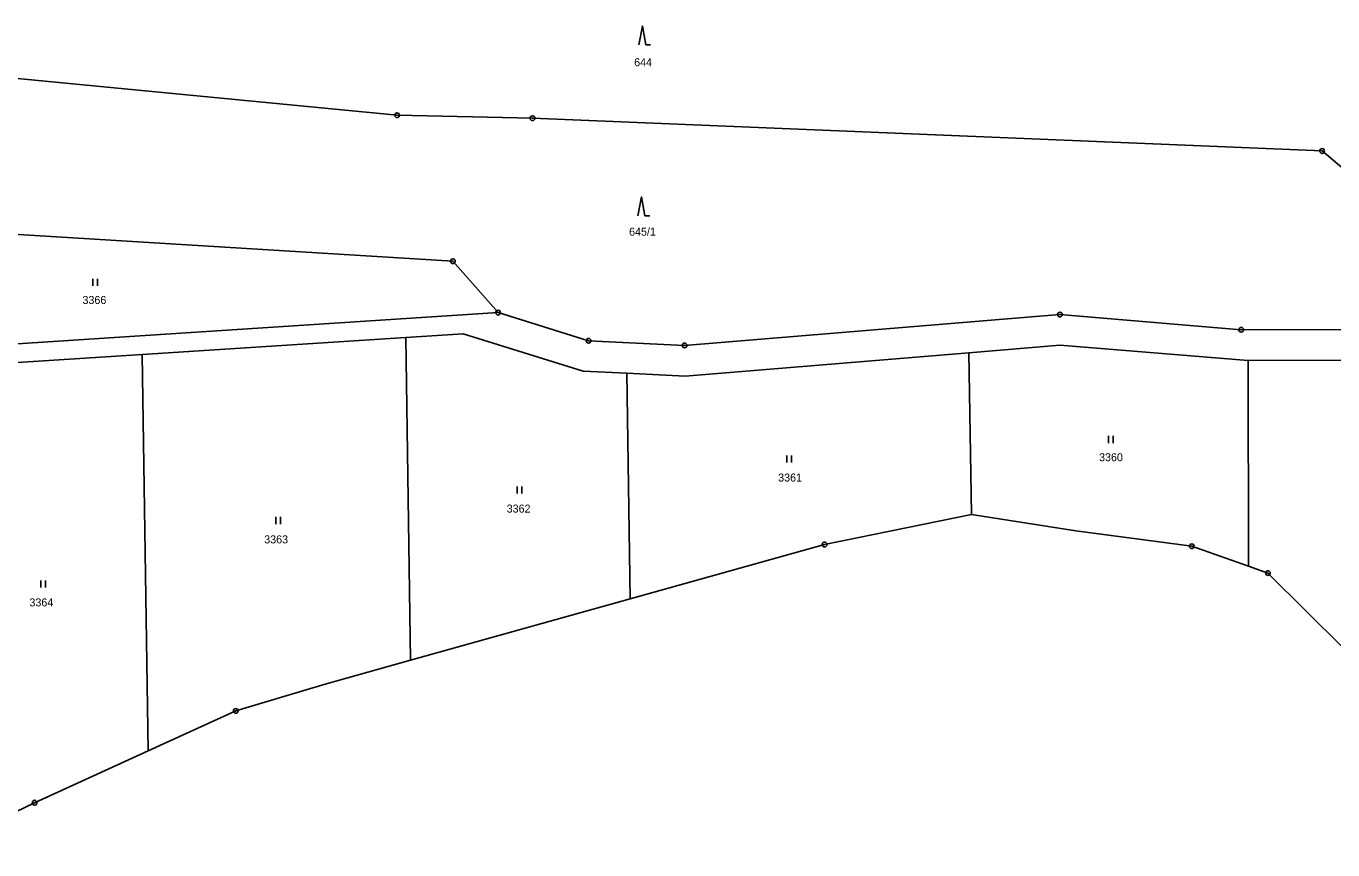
# Model space of a CAD drawing. Extents: x -618848 to -615803, y -1044450 to -1042254.
# Drawn here: x -618500.4 to -618222.9, y -1044104.3 to -1043929.4 of the extents above; entities that cross this region are included whole.
import ezdxf
from ezdxf.enums import TextEntityAlignment as Align

# ---------------------------------------------------------------- set-up
doc = ezdxf.new("R2010")
doc.units = 0
doc.header["$LTSCALE"] = 0.68
for name, color, linetype, lineweight in [('1', 7, 'Continuous', 25), ('3', 7, 'Continuous', 25), ('8', 7, 'Continuous', 25)]:
    doc.layers.add(name, color=color, linetype=linetype, lineweight=lineweight)
doc.layers.add('2', color=7, linetype='Continuous')

msp = doc.modelspace()

# ---------------------------------------------------------------- linework, layer by layer
at = {"layer": '1'}
for p, q in [((-618421.62, -1043948.29), (-618536.13, -1043937.25)), ((-618392.85, -1043948.94), (-618421.62, -1043948.29)), ((-618225.13, -1043955.89), (-618392.85, -1043948.94)), ((-618219.08, -1043960.95), (-618225.13, -1043955.89)), ((-618542.01, -1043971.2), (-618409.76, -1043979.3)), ((-618409.76, -1043979.3), (-618400.15, -1043990.22)), ((-618540.13, -1043999.28), (-618400.15, -1043990.22)), ((-618400.15, -1043990.22), (-618380.94, -1043996.19)), ((-618360.55, -1043997.17), (-618280.83, -1043990.62)), ((-618280.83, -1043990.62), (-618242.32, -1043993.85)), ((-618242.32, -1043993.85), (-618214.39, -1043993.81)), ((-618475.75, -1043999.12), (-618419.77, -1043995.5)), ((-618419.77, -1043995.5), (-618407.6, -1043994.71)), ((-618419.77, -1043995.5), (-618418.76, -1044064.03)), ((-618407.6, -1043994.71), (-618382.08, -1044002.64)), ((-618380.94, -1043996.19), (-618360.55, -1043997.17)), ((-618521.01, -1044002.05), (-618475.75, -1043999.12)), ((-618474.5, -1044083.28), (-618475.75, -1043999.12)), ((-618360.44, -1044003.68), (-618300.15, -1043998.72)), ((-618300.15, -1043998.72), (-618280.84, -1043997.14)), ((-618300.15, -1043998.72), (-618299.64, -1044033.06)), ((-618280.84, -1043997.14), (-618240.84, -1044000.41)), ((-618240.84, -1044000.41), (-618212.51, -1044000.31)), ((-618240.84, -1044000.41), (-618240.8, -1044044.05)), ((-618382.08, -1044002.64), (-618372.81, -1044003.08)), ((-618372.81, -1044003.08), (-618372.1, -1044050.99)), ((-618372.81, -1044003.08), (-618360.44, -1044003.68)), ((-618330.8, -1044039.45), (-618299.64, -1044033.06)), ((-618277.43, -1044036.55), (-618299.64, -1044033.06)), ((-618252.84, -1044039.82), (-618277.43, -1044036.55)), ((-618372.1, -1044050.99), (-618330.8, -1044039.45)), ((-618240.8, -1044044.05), (-618252.84, -1044039.82)), ((-618236.64, -1044045.51), (-618240.8, -1044044.05)), ((-618220.58, -1044061.44), (-618236.64, -1044045.51)), ((-618418.76, -1044064.03), (-618372.1, -1044050.99)), ((-618418.76, -1044064.03), (-618436.86, -1044069.09)), ((-618436.86, -1044069.09), (-618455.89, -1044074.8)), ((-618455.89, -1044074.8), (-618474.5, -1044083.28)), ((-618498.61, -1044094.27), (-618474.5, -1044083.28)), ((-618498.61, -1044094.27), (-618519.5, -1044104.29))]:
    msp.add_line(p, q, dxfattribs=at)
at = {"layer": '3'}
for p, q in [((-618368.77, -1043933.38), (-618367.774, -1043933.38)), ((-618368.96, -1043969.64), (-618367.964, -1043969.64)), ((-618486.251, -1043984.54), (-618486.251, -1043983.04)), ((-618485.25, -1043984.54), (-618485.25, -1043983.04)), ((-618270.531, -1044017.9), (-618270.531, -1044016.4)), ((-618269.53, -1044017.9), (-618269.53, -1044016.4)), ((-618338.811, -1044022.03), (-618338.811, -1044020.53)), ((-618337.81, -1044022.03), (-618337.81, -1044020.53)), ((-618396.121, -1044028.64), (-618396.121, -1044027.14)), ((-618395.12, -1044028.64), (-618395.12, -1044027.14)), ((-618447.391, -1044035.1), (-618447.391, -1044033.6)), ((-618446.39, -1044035.1), (-618446.39, -1044033.6)), ((-618497.291, -1044048.57), (-618497.291, -1044047.07)), ((-618496.29, -1044048.57), (-618496.29, -1044047.07))]:
    msp.add_line(p, q, dxfattribs=at)
for points in [[(-618368.77, -1043933.38), (-618369.52, -1043929.38), (-618370.27, -1043933.38)], [(-618368.96, -1043969.64), (-618369.71, -1043965.64), (-618370.46, -1043969.64)]]:
    msp.add_lwpolyline(points, dxfattribs=at)
at = {"layer": '8'}
for centre, radius in [((-618421.62, -1043948.2899), 0.5), ((-618421.62, -1043948.2899), 0.0303), ((-618392.85, -1043948.9399), 0.5), ((-618392.85, -1043948.9399), 0.0303), ((-618225.13, -1043955.8899), 0.5), ((-618225.13, -1043955.8899), 0.0303), ((-618409.76, -1043979.2999), 0.5), ((-618409.76, -1043979.2999), 0.0303), ((-618400.15, -1043990.2199), 0.5), ((-618400.15, -1043990.2199), 0.0303), ((-618280.83, -1043990.6199), 0.5), ((-618280.83, -1043990.6199), 0.0303), ((-618242.32, -1043993.8499), 0.5), ((-618242.32, -1043993.8499), 0.0303), ((-618380.94, -1043996.1899), 0.5), ((-618380.94, -1043996.1899), 0.0303), ((-618360.55, -1043997.1699), 0.5), ((-618360.55, -1043997.1699), 0.0303), ((-618330.8, -1044039.4499), 0.5), ((-618330.8, -1044039.4499), 0.0303), ((-618252.84, -1044039.8199), 0.5), ((-618252.84, -1044039.8199), 0.0303), ((-618236.64, -1044045.5099), 0.5), ((-618236.64, -1044045.5099), 0.0303), ((-618455.89, -1044074.7999), 0.5), ((-618455.89, -1044074.7999), 0.0303), ((-618498.61, -1044094.2699), 0.5), ((-618498.61, -1044094.2699), 0.0303)]:
    msp.add_circle(centre, radius, dxfattribs=at)

# ---------------------------------------------------------------- texts
at = {"layer": '2'}
for s, p in [('644', (-618369.359, -1043937.895)), ('645/1', (-618369.49, -1043973.875))]:
    msp.add_text(s, height=1.7, dxfattribs=at).set_placement(p, align=Align.CENTER)
for s, p in [('3366', (-618488.43, -1043988.375)), ('3360', (-618272.51, -1044021.775)), ('3361', (-618340.67, -1044026.085)), ('3362', (-618398.33, -1044032.675)), ('3363', (-618449.83, -1044039.215)), ('3364', (-618499.7, -1044052.595))]:
    msp.add_text(s, height=1.7, dxfattribs=at).set_placement(p)

doc.saveas('drawing.dxf')
